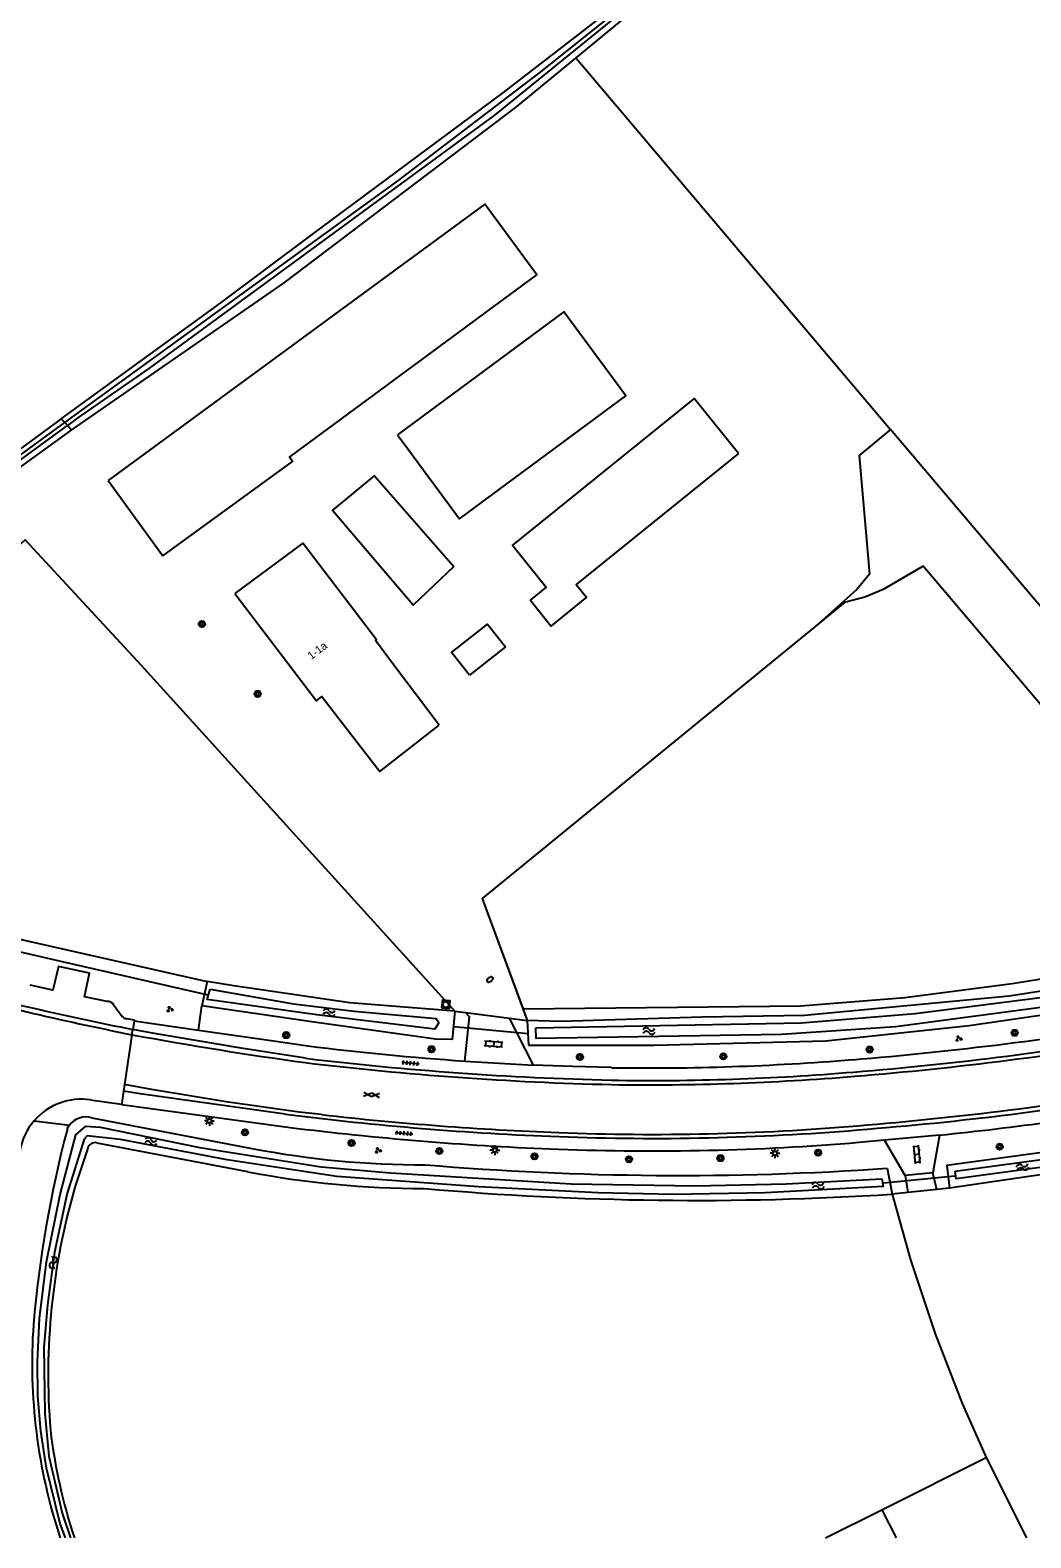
# Model space of a CAD drawing. Extents: x 136000 to 141014, y 402000 to 403500.
# Drawn here: x 136150.5 to 136277.5, y 402000 to 402191.4 of the extents above; entities that cross this region are included whole.
import ezdxf

# ---------------------------------------------------------------- set-up
doc = ezdxf.new("R2010")
doc.units = 0
for name, color, linetype in [('gg-afsc-draadraster', 7, 'Continuous'), ('gg-afsc-erfafscheiding', 7, 'Continuous'), ('gg-afsc-lijn draadraster', 7, 'Continuous'), ('gg-anno-huisnummerreeks BGT', 7, 'Continuous'), ('gg-bbg-bijgebouw', 7, 'Continuous'), ('gg-bbg-gedigitaliseerde bebouwing', 7, 'Continuous'), ('gg-bbg-gedigitaliseerde bijgebouw', 7, 'Continuous'), ('gg-bbg-hoofdgebouw', 7, 'Continuous'), ('gg-bbg-open loods', 7, 'Continuous'), ('gg-knt-bronhoudergrens', 7, 'Continuous'), ('gg-knt-verharding', 7, 'Continuous'), ('gg-kntw-bovenkant insteek waterloop', 7, 'Continuous'), ('gg-kntw-waterlijn', 7, 'Continuous'), ('gg-kwrk-duiker nz buis', 7, 'Continuous'), ('gt-grn-groengrens', 7, 'Continuous'), ('gt-grn-vlakafsluiter', 7, 'Continuous'), ('gt-grn-weggrens', 7, 'Continuous'), ('gt-symb-boom', 7, 'Continuous'), ('gt-symb-brandkraan', 7, 'Continuous'), ('gt-symb-gesloten verharding', 7, 'Continuous'), ('gt-symb-groenvak', 7, 'Continuous'), ('gt-symb-klinker verharding', 7, 'Continuous'), ('gt-symb-lichtmast', 7, 'Continuous'), ('gt-symb-rioolschacht', 7, 'Continuous'), ('gt-symb-tegel verharding', 7, 'Continuous'), ('gt-symb-watersymbool', 7, 'Continuous')]:
    doc.layers.add(name, color=color, linetype=linetype)

# ---------------------------------------------------------------- blocks, each defined once
blk = doc.blocks.new('gt0-KL1')
at = {"layer": 'gt-symb-klinker verharding'}
for p, q in [((-1.15, 0.3), (1.15, 0.3)), ((-1, -0.3), (-1, 0.3)), ((-0.5, 0.3), (-0.5, 0.45)), ((0, -0.3), (0, 0.3)), ((0.5, 0.3), (0.5, 0.45)), ((1, -0.3), (1, 0.3)), ((-1.15, -0.3), (1.15, -0.3)), ((-0.5, -0.45), (-0.5, -0.3)), ((0.5, -0.45), (0.5, -0.3))]:
    blk.add_line(p, q, dxfattribs=at)
blk = doc.blocks.new('gt0-BOOM')
at = {"layer": 'gt-symb-boom'}
for radius in [0.4, 0.2]:
    blk.add_circle((0, 0), radius, dxfattribs=at)
blk = doc.blocks.new('gt0-WA')
at = {"layer": 'gt-symb-watersymbool'}
for centre, start, end in [((-0.32, 0.02), 28.0725, 151.9275), ((0.43, 0.42), 208.0725, 331.9275), ((-0.32, -0.43), 28.0725, 151.9275), ((0.43, -0.03), 208.0725, 331.9275)]:
    blk.add_arc(centre, 0.425, start, end, dxfattribs=at)
blk = doc.blocks.new('gt0-LMAST')
at = {"layer": 'gt-symb-lichtmast'}
for p, q in [((-0.18, 0.17), (-0.45, 0.44)), ((0, 0.25), (0, 0.62)), ((0.17, 0.17), (0.44, 0.44)), ((-0.25, 0), (-0.63, 0)), ((-0.18, -0.18), (-0.45, -0.45)), ((0, -0.25), (0, -0.63)), ((0.44, -0.45), (0.17, -0.18)), ((0.25, 0), (0.62, 0))]:
    blk.add_line(p, q, dxfattribs=at)
blk.add_circle((0, 0), 0.25, dxfattribs=at)
blk = doc.blocks.new('gt0-GRVAK')
at = {"layer": 'gt-symb-groenvak'}
for p, q in [((-0.11, 0.19), (-0.23, 0.24)), ((-0.18, 0.15), (0.09, 0.15)), ((-0.09, 0.21), (-0.16, 0.32)), ((-0.05, 0.21), (-0.05, 0.39)), ((0, 0.21), (0.06, 0.32)), ((0.02, 0.19), (0.13, 0.24)), ((0.26, -0.05), (0.2, 0.06)), ((0.31, -0.05), (0.31, 0.13)), ((0.35, -0.05), (0.41, 0.06)), ((-0.24, -0.23), (-0.36, -0.18)), ((-0.32, -0.26), (-0.05, -0.26)), ((-0.23, -0.21), (-0.29, -0.1)), ((-0.18, -0.2), (-0.18, -0.02)), ((-0.14, -0.21), (-0.07, -0.1)), ((-0.12, -0.23), (0, -0.18)), ((0.24, -0.07), (0.12, -0.02)), ((0.17, -0.11), (0.44, -0.11)), ((0.37, -0.07), (0.49, -0.02))]:
    blk.add_line(p, q, dxfattribs=at)
blk = doc.blocks.new('gt0-RS')
at = {"layer": 'gt-symb-rioolschacht'}
blk.add_lwpolyline([(-0.5, -0.5), (0.5, -0.5), (0.5, 0.5), (-0.5, 0.5)], close=True, dxfattribs=at)
blk.add_circle((0, 0), 0.375, dxfattribs=at)
blk = doc.blocks.new('gt0-BR')
at = {"layer": 'gt-symb-brandkraan'}
for centre, radius, start, end in [((-0.24, 0), 0.206, 107.5669, 252.4331), ((0.6, -2.66), 3, 106.892, 107.5669), ((0, -0.69), 0.938, 73.108, 106.892), ((-0.6, -2.66), 3, 72.4331, 73.108), ((0.24, 0), 0.206, 287.567, 72.4331), ((0.6, 2.66), 3, 252.4331, 253.108), ((0, 0.69), 0.938, 253.108, 286.8921), ((-0.6, 2.66), 3, 286.8921, 287.567)]:
    blk.add_arc(centre, radius, start, end, dxfattribs=at)
blk = doc.blocks.new('gt0-TEG1')
at = {"layer": 'gt-symb-tegel verharding'}
for p, q in [((-1.12, 0), (1.12, 0)), ((-0.9, -0.25), (-0.9, 0.25)), ((-0.45, -0.25), (-0.45, 0.25)), ((0, -0.25), (0, 0.25)), ((0.45, -0.25), (0.45, 0.25)), ((0.9, -0.25), (0.9, 0.25))]:
    blk.add_line(p, q, dxfattribs=at)
blk = doc.blocks.new('gt0-GESVH1')
at = {"layer": 'gt-symb-gesloten verharding'}
for p, q in [((-0.99, -0.26), (0.01, 0.24)), ((0.01, -0.26), (-0.99, 0.24)), ((0.01, 0.24), (1.01, -0.26)), ((1.01, 0.24), (0.01, -0.26))]:
    blk.add_line(p, q, dxfattribs=at)

msp = doc.modelspace()

# ---------------------------------------------------------------- linework, layer by layer
at = {"layer": 'gg-afsc-draadraster'}
msp.add_line((136220.01, 402187.52), (136259.64, 402140.69), dxfattribs=at)
at = {"layer": 'gg-afsc-erfafscheiding'}
for p, q in [((136131.58, 402079.95), (136172.93, 402070.61)), ((136204.39, 402066.87), (136205.73, 402066.7)), ((136205.73, 402066.7), (136211.31, 402065.97)), ((136211.31, 402065.97), (136213.57, 402065.67)), ((136261.85, 402043.84), (136259.88, 402043.63)), ((136265.54, 402044.23), (136261.85, 402043.84)), ((136267.15, 402044.4), (136265.54, 402044.23))]:
    msp.add_line(p, q, dxfattribs=at)
at = {"layer": 'gg-afsc-lijn draadraster'}
msp.add_line((136220.01, 402187.52), (136259.64, 402140.69), dxfattribs=at)
msp.add_lwpolyline([(136259.64, 402140.69), (136255.67, 402137.38), (136256.99, 402122.3), (136255.39, 402120.39), (136250.51, 402116.02), (136207.86, 402081.16), (136213.57, 402065.67)], dxfattribs=at)
at = {"layer": 'gg-bbg-bijgebouw'}
for p, q in [((136160.39, 402134.19), (136167.33, 402124.63)), ((136258.55, 402003.54), (136271.81, 402010.18)), ((136258.55, 402003.54), (136260.37, 402000))]:
    msp.add_line(p, q, dxfattribs=at)
at = {"layer": 'gg-bbg-gedigitaliseerde bebouwing'}
msp.add_lwpolyline([(136202.39, 402103.13), (136196.76, 402110.58), (136194.32, 402113.91), (136194.42, 402113.99), (136185.08, 402126.27), (136176.44, 402119.87)], dxfattribs=at)
at = {"layer": 'gg-bbg-gedigitaliseerde bijgebouw'}
msp.add_line((136271.81, 402010.18), (136276.91, 402000), dxfattribs=at)
for points in [[(136167.33, 402124.63), (136183.78, 402136.62), (136183.37, 402137.18), (136214.79, 402160.29), (136208.19, 402169.29), (136160.39, 402134.19)], [(136240.35, 402137.65), (136234.73, 402144.61), (136211.68, 402125.98), (136215.98, 402120.66), (136213.94, 402119.02)], [(136240.35, 402137.65), (136219.75, 402120.99), (136221.08, 402119.4), (136216.54, 402115.71), (136213.94, 402119.02)], [(136204.25, 402123.29), (136199.08, 402118.39), (136188.84, 402130.41), (136194.17, 402134.8), (136204.25, 402123.29)], [(136206.23, 402109.48), (136203.96, 402112.36), (136208.52, 402115.96), (136210.79, 402113.08), (136206.23, 402109.48)]]:
    msp.add_lwpolyline(points, dxfattribs=at)
at = {"layer": 'gg-bbg-hoofdgebouw'}
msp.add_lwpolyline([(136176.44, 402119.87), (136186.82, 402106.25), (136187.5, 402106.78), (136194.85, 402097.29), (136202.39, 402103.13)], dxfattribs=at)
at = {"layer": 'gg-bbg-open loods'}
msp.add_lwpolyline([(136197.09, 402140.02), (136204.96, 402129.36), (136226.07, 402144.94), (136218.2, 402155.6), (136197.09, 402140.02)], dxfattribs=at)
at = {"layer": 'gg-knt-bronhoudergrens'}
for p, q in [((136219.72, 402187.86), (136220.01, 402187.52)), ((136204.39, 402066.87), (136164.56, 402110.75)), ((136213.04, 402067.12), (136213.57, 402065.67)), ((136251.43, 402000), (136258.55, 402003.54))]:
    msp.add_line(p, q, dxfattribs=at)
for points in [[(136313.85, 402076.56), (136312.15, 402079.55), (136303.38, 402088.96), (136281.08, 402115.43), (136259.64, 402140.69)], [(136164.56, 402110.75), (136149.84, 402126.66), (136147.96, 402124.92), (136145.26, 402128.13), (136147.1, 402129.67), (136144.62, 402132.63)], [(136299.42, 402074.19), (136298.67, 402081.08), (136295.23, 402085.98), (136285.51, 402097.75), (136275.92, 402109.06), (136263.81, 402123.35), (136258.72, 402120.37), (136256.39, 402119.38), (136253.82, 402118.7), (136250.51, 402116.02), (136207.86, 402081.16), (136213.04, 402067.12)], [(136259.88, 402043.63), (136262.21, 402035.27), (136265.32, 402025.89), (136268.74, 402017.05), (136271.81, 402010.18)]]:
    msp.add_lwpolyline(points, dxfattribs=at)
at = {"layer": 'gg-knt-verharding'}
for p, q in [((136161.1, 402067.59), (136162.16, 402066.18)), ((136163.68, 402065.63), (136171.82, 402064.45)), ((136214.37, 402060.01), (136211.31, 402065.97)), ((136163.39, 402063.86), (136162.45, 402057.54)), ((136205.63, 402060.52), (136214.37, 402060.01)), ((136162.45, 402057.54), (136162.32, 402056.68)), ((136162.05, 402055.01), (136158.15, 402055.57)), ((136162.05, 402055.01), (136184.42, 402051.97)), ((136265.88, 402051.12), (136258.91, 402050.47)), ((136265.88, 402051.12), (136265.03, 402046.35)), ((136258.91, 402050.47), (136255.65, 402050.2)), ((136261.51, 402046.01), (136258.91, 402050.47)), ((136265.03, 402046.35), (136261.51, 402046.01)), ((136261.51, 402046.01), (136261.85, 402043.84)), ((136265.54, 402044.23), (136265.03, 402046.35))]:
    msp.add_line(p, q, dxfattribs=at)
for points in [[(136160.26, 402068.08), (136157.35, 402068.68), (136158.02, 402071.69), (136154.05, 402072.52), (136153.34, 402069.52), (136150.47, 402070.15)], [(136205.63, 402060.52), (136206.23, 402066.13), (136205.73, 402066.7)], [(136162.69, 402065.9), (136163.66, 402065.75), (136163.68, 402065.63)], [(136185.43, 402060.87), (136177.27, 402062.16), (136166.02, 402064.04), (136163.5, 402064.53)], [(136171.82, 402064.45), (136182.24, 402062.96), (136185.72, 402062.44)], [(136224.26, 402059.68), (136219.31, 402059.81), (136214.37, 402060.01)], [(136162.32, 402056.68), (136162.11, 402055.21), (136162.05, 402055.01)], [(136182.84, 402053.78), (136164.45, 402056.34), (136162.32, 402056.68)], [(136187.46, 402053.72), (136184.63, 402054.04), (136175.35, 402055.34), (136166.11, 402056.85), (136162.45, 402057.54)]]:
    msp.add_lwpolyline(points, dxfattribs=at)
for centre, radius, start, end in [((136239.91, 402447.14), 390.84, 254.713, 258.7087), ((136232.07, 402415.72), 357.82, 254.8352, 258.9513), ((136160.32, 402067.23), 0.858, 25.157, 94.0496), ((136162.71, 402066.59), 0.689, 216.0822, 268.1626), ((136218.94, 402502.4), 443.16, 274.6411, 279.6919), ((136254.99, 402562.98), 507.46, 259.6004, 262.1139), ((136232.22, 402441.07), 381.48, 262.9985, 266.0033), ((136221.84, 402472.55), 414.75, 274.5818, 279.9955), ((136221.63, 402473.27), 416.03, 274.6205, 280.0052), ((136234.01, 402468.06), 410.08, 263.1968, 268.6349), ((136228.93, 402377.22), 317.58, 269.1574, 274.6723), ((136233.9, 402464.84), 407.42, 263.1584, 268.6438), ((136229.41, 402363.19), 305.14, 269.0288, 274.806), ((136228.76, 402378.92), 321.42, 269.1965, 274.7082), ((136219.83, 402492.16), 441.29, 274.6363, 279.6854), ((136156.93, 402047.8), 7.87, 81.0934, 139.1853), ((136223.49, 402463.77), 413.23, 274.4467, 279.8544), ((136223.77, 402461.67), 412.71, 275.8571, 279.8653), ((136156.92, 402047.8), 7.87, 139.1545, 170.8311), ((136232.21, 402442.9), 392.24, 262.7696, 267.8657), ((136232.84, 402455.54), 404.38, 263.556, 267.8341), ((136232.91, 402450.44), 401.41, 263.0611, 267.8028), ((136229.71, 402353.21), 302, 267.6949, 274.8992), ((136229.55, 402364.64), 313.94, 267.8181, 274.7465), ((136229.32, 402366.79), 317.68, 267.8711, 274.7526)]:
    msp.add_arc(centre, radius, start, end, dxfattribs=at)
at = {"layer": 'gg-kntw-bovenkant insteek waterloop'}
for p, q in [((136172.93, 402070.61), (136172.25, 402067.51)), ((136213.57, 402065.67), (136213.74, 402062.54)), ((136158.31, 402053.32), (136178.62, 402049.43)), ((136157.78, 402049.48), (136156.19, 402044.64)), ((136158.92, 402050.15), (136178.05, 402046.48)), ((136285.89, 402047.15), (136267.15, 402044.4)), ((136259.24, 402046.91), (136259.88, 402043.63))]:
    msp.add_line(p, q, dxfattribs=at)
for points in [[(136154.43, 402142.05), (136174.68, 402156.77), (136186.1, 402165.29), (136210.53, 402183.46), (136223.92, 402193.76), (136238.79, 402205.83), (136250.21, 402214.93), (136257.61, 402220.87), (136266.65, 402228.33), (136309.4, 402262.69), (136324.91, 402275.29), (136351.53, 402296.65)], [(136392.32, 402249.81), (136363.85, 402281.11), (136351.14, 402294.37), (136347.19, 402291.24), (136341.18, 402286.27), (136334.22, 402280.56), (136302.3, 402254.81), (136291.4, 402245.95), (136265.06, 402224.91), (136258.94, 402219.98), (136250.31, 402213.09), (136245.53, 402209.23), (136239.11, 402203.85), (136219.72, 402187.86)], [(136219.72, 402187.86), (136212.15, 402181.62), (136182.67, 402159.29), (136155.72, 402140.63)], [(136154.43, 402142.05), (136121.34, 402117.72), (136108.5, 402107.8), (136094.9, 402097.97)], [(136155.72, 402140.63), (136153.58, 402139.06), (136144.62, 402132.63)], [(136299.49, 402072.61), (136274.71, 402068.74), (136248.75, 402066.32), (136235.7, 402066.08), (136217.87, 402065.55), (136213.57, 402065.67)], [(136213.74, 402062.54), (136229.62, 402062.53), (136251.47, 402063.1), (136269.63, 402065.04), (136287.97, 402067.68), (136306.28, 402071.24), (136314.69, 402073.53)], [(136204.39, 402066.87), (136191.04, 402067.9), (136176.33, 402070.07), (136172.93, 402070.61)], [(136204.39, 402066.87), (136204.05, 402063.26), (136201.93, 402063.31), (136186.5, 402065.44), (136172.25, 402067.51)], [(136155.19, 402051.94), (136155.29, 402052.18), (136155.45, 402052.39)], [(136285.89, 402047.15), (136285.42, 402049.8), (136266.8, 402047.26), (136267.15, 402044.4)]]:
    msp.add_lwpolyline(points, dxfattribs=at)
for centre, radius, start, end in [((136157.58, 402050.72), 2.7, 74.3438, 141.9348), ((136298.56, 402014.35), 148.21, 165.3096, 175.0711), ((136158.73, 402049.17), 0.997, 79.0431, 162.0067), ((136200.44, 402163.23), 115.88, 259.1459, 270.077), ((136232.79, 402431.34), 385.34, 265.2083, 273.9357), ((136200.43, 402163.2), 118.85, 259.1464, 270.0168), ((136238.24, 402020.66), 85.48, 163.7101, 184.7021), ((136234.93, 402434.21), 391.38, 264.9486, 273.655), ((136221.76, 402022.18), 71.04, 176.0418, 198.1937), ((136222.54, 402022.02), 70, 186.8668, 198.3366)]:
    msp.add_arc(centre, radius, start, end, dxfattribs=at)
at = {"layer": 'gg-kntw-waterlijn'}
for points in [[(136154.87, 402141.57), (136197.27, 402172.34), (136215.28, 402186.08), (136228.64, 402196.8), (136260.64, 402222.76), (136287.79, 402244.57), (136305.49, 402258.74), (136312.06, 402264.16), (136345.68, 402291.32), (136350.76, 402295.46), (136350.98, 402295.6), (136351.77, 402295.6)], [(136351.49, 402294.9), (136351.15, 402294.9), (136334.39, 402281.44), (136305.34, 402258.04), (136264.35, 402225.09), (136240.57, 402206.03), (136225.27, 402193.45), (136209.4, 402180.57), (136165.52, 402148.4), (136156.7, 402142.27), (136155.22, 402141.18)], [(136091.58, 402094.67), (136103.49, 402103.53), (136125.85, 402120.39), (136154.87, 402141.57)], [(136092.28, 402094.25), (136098, 402098.71), (136122.21, 402117.08), (136155.22, 402141.18)], [(136214.67, 402064.73), (136248.36, 402065.35), (136262.79, 402066.57), (136282.32, 402069.05), (136297.09, 402071.37), (136313.54, 402075.18), (136313.74, 402074.29), (136305.93, 402072.04), (136294.39, 402069.76), (136280, 402067.49), (136260.28, 402064.87), (136245.81, 402063.89), (136214.7, 402063.39), (136214.67, 402064.73)], [(136173.3, 402069.66), (136183.9, 402067.8), (136191.61, 402066.85), (136201.98, 402065.91), (136202.33, 402065.4), (136201.82, 402064.58), (136186.84, 402066.37), (136172.93, 402068.31), (136173.3, 402069.66)], [(136154.94, 402000), (136154.3, 402001.78), (136152.53, 402008.83), (136151.82, 402013.53), (136151.46, 402018.02), (136151.42, 402022.32), (136151.66, 402027.82), (136152.55, 402035.04), (136154.3, 402043.59), (136156.29, 402051.16), (136157.52, 402052.26), (136159.38, 402052.13), (136172.01, 402049.53), (136187.42, 402047.09), (136196.19, 402046.32), (136219.13, 402044.92), (136234.91, 402044.66), (136246.43, 402044.92), (136258.57, 402045.55), (136258.72, 402044.58), (136243.74, 402043.77), (136232.06, 402043.58), (136222.58, 402043.8), (136207.41, 402044.57), (136189.38, 402045.87), (136175.49, 402047.99), (136161.93, 402050.57), (136157.72, 402051.02), (136157.31, 402050.61), (136155.19, 402043.76), (136153.58, 402036.28), (136152.69, 402029.57), (136152.21, 402024.22), (136152.32, 402015.79), (136152.86, 402010.36), (136154.52, 402003.13), (136155.58, 402000)], [(136267.87, 402046.53), (136285.07, 402048.85), (136285.2, 402047.88), (136267.99, 402045.56), (136267.87, 402046.53)]]:
    msp.add_lwpolyline(points, dxfattribs=at)
at = {"layer": 'gg-kwrk-duiker nz buis'}
for p, q in [((136154.21, 402073.21), (136130.37, 402078.68)), ((136173.06, 402068.89), (136154.21, 402073.21)), ((136213.67, 402063.99), (136204.2, 402064.85)), ((136267.82, 402045.91), (136258.8, 402045.03))]:
    msp.add_line(p, q, dxfattribs=at)
at = {"layer": 'gt-grn-groengrens'}
for p, q in [((136171.82, 402064.45), (136172.25, 402067.51)), ((136150.97, 402052.94), (136155.45, 402052.39))]:
    msp.add_line(p, q, dxfattribs=at)
at = {"layer": 'gt-grn-vlakafsluiter'}
for p, q in [((136154.43, 402142.05), (136154.87, 402141.57)), ((136154.87, 402141.57), (136155.22, 402141.18)), ((136155.22, 402141.18), (136155.72, 402140.63))]:
    msp.add_line(p, q, dxfattribs=at)
msp.add_lwpolyline([(136299.42, 402074.19), (136275.11, 402070.33), (136261.49, 402068.54), (136248.29, 402067.48), (136213.04, 402067.12)], dxfattribs=at)
at = {"layer": 'gt-grn-weggrens'}
for p in [(136163.39, 402063.86), (136163.68, 402065.63)]:
    msp.add_line(p, (136163.5, 402064.53), dxfattribs=at)

# ---------------------------------------------------------------- block references
at = {"layer": 'gt-symb-boom'}
for p in [(136172.27, 402115.98), (136179.35, 402107.12), (136275.42, 402064.1), (136182.97, 402063.81), (136201.41, 402062.02), (136220.24, 402061.02), (136238.44, 402061.11), (136257.02, 402061.98), (136177.74, 402051.46), (136191.26, 402050.11), (136202.4, 402049.1), (136250.48, 402048.9), (136273.51, 402049.65), (136214.48, 402048.42), (136226.47, 402048.05), (136238.08, 402048.19)]:
    msp.add_blockref('gt0-BOOM', p, dxfattribs=at)
at = {"layer": 'gt-symb-brandkraan', "rotation": 37.316974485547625}
msp.add_blockref('gt0-BR', (136208.82, 402070.87), dxfattribs=at)
at = {"layer": 'gt-symb-gesloten verharding', "rotation": -4.012171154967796}
msp.add_blockref('gt0-GESVH1', (136193.79, 402056.23), dxfattribs=at)
at = {"layer": 'gt-symb-groenvak'}
for p in [(136168.19, 402067.1), (136268.3, 402063.37), (136194.61, 402049.18)]:
    msp.add_blockref('gt0-GRVAK', p, dxfattribs=at)
at = {"layer": 'gt-symb-klinker verharding'}
for p, rotation in [((136209.28, 402062.67), 176.10210376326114), ((136263.03, 402048.66), 95.85309130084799)]:
    msp.add_blockref('gt0-KL1', p, dxfattribs=dict(at, rotation=rotation))
at = {"layer": 'gt-symb-lichtmast'}
for p in [(136173.22, 402052.92), (136209.44, 402049.22), (136245, 402048.81)]:
    msp.add_blockref('gt0-LMAST', p, dxfattribs=at)
at = {"layer": 'gt-symb-rioolschacht', "rotation": -4.992081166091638}
msp.add_blockref('gt0-RS', (136203.24, 402067.71), dxfattribs=at)
at = {"layer": 'gt-symb-tegel verharding'}
for p, rotation in [((136198.74, 402060.26), -5.391463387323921), ((136197.92, 402051.35), -4.820766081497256)]:
    msp.add_blockref('gt0-TEG1', p, dxfattribs=dict(at, rotation=rotation))
at = {"layer": 'gt-symb-watersymbool'}
for p, rotation in [((136188.36, 402066.68), 0.973934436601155), ((136228.95, 402064.33), 6.030008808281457), ((136165.74, 402050.32), -4.0121711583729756), ((136276.36, 402047.03), 16.02410965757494), ((136250.41, 402044.7), 8.972626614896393), ((136153.39, 402034.88), 85.98782884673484)]:
    msp.add_blockref('gt0-WA', p, dxfattribs=dict(at, rotation=rotation))

# ---------------------------------------------------------------- texts
at = {"layer": 'gg-anno-huisnummerreeks BGT'}
msp.add_text('1-1a', height=1, rotation=37.3, dxfattribs=at).set_placement((136186.15, 402111.42))

doc.saveas('drawing.dxf')
